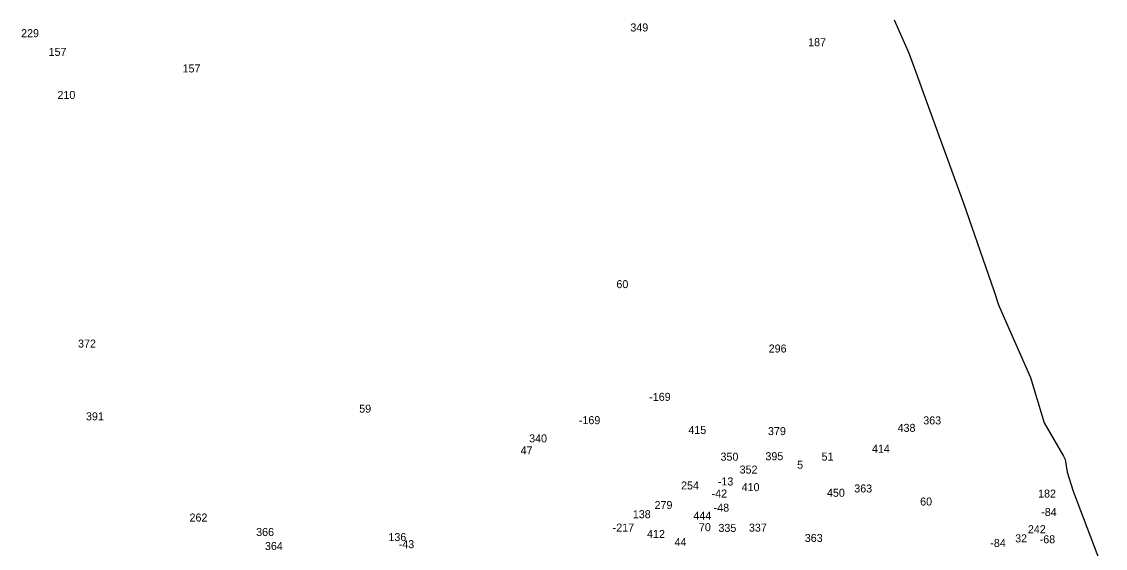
# Model space of a CAD drawing. Extents: x -784109 to -782312, y -974244 to -970866.
# Drawn here: x -783385 to -782606, y -972930 to -972551 of the extents above; entities that cross this region are included whole.
import ezdxf

# ---------------------------------------------------------------- set-up
doc = ezdxf.new("R2010")
doc.units = 0
doc.layers.add('Vrstva 13', color=7, linetype='Continuous')
doc.layers.add('Vrstva 24', color=7, linetype='Continuous')

msp = doc.modelspace()

# ---------------------------------------------------------------- linework, layer by layer
at = {"layer": 'Vrstva 13'}
for p, q in [((-782757.42, -972549.41), (-782746.7, -972573.88)), ((-782746.7, -972573.88), (-782729.15, -972622.14)), ((-782729.15, -972622.14), (-782707.62, -972681.32)), ((-782707.62, -972681.32), (-782685.79, -972744.19)), ((-782685.79, -972744.19), (-782682.37, -972754.55)), ((-782682.37, -972754.55), (-782678.23, -972763.97)), ((-782678.23, -972763.97), (-782659.4, -972806.95)), ((-782659.4, -972806.95), (-782649.62, -972839.48)), ((-782649.62, -972839.48), (-782635.59, -972863.43)), ((-782635.59, -972863.43), (-782634.41, -972866.03)), ((-782634.41, -972866.03), (-782633.06, -972875.09)), ((-782633.06, -972875.09), (-782628.66, -972888.81)), ((-782628.66, -972888.81), (-782605.57, -972949.88))]:
    msp.add_line(p, q, dxfattribs=at)

# ---------------------------------------------------------------- texts
at = {"layer": 'Vrstva 24'}
for s, p in [('349', (-782947.262, -972557.712)), ('229', (-783385.536, -972561.812)), ('187', (-782819.367, -972568.302)), ('157', (-783365.767, -972575.272)), ('157', (-783269.427, -972587.222)), ('210', (-783359.402, -972606.322)), ('60', (-782957.303, -972742.552)), ('372', (-783344.585, -972785.332)), ('296', (-782847.739, -972788.902)), ('-169', (-782933.688, -972823.692)), ('59', (-783142.316, -972832.202)), ('391', (-783338.899, -972837.712)), ('-169', (-782984.3, -972840.48)), ('363', (-782736.546, -972840.652)), ('415', (-782905.511, -972847.542)), ('379', (-782848.248, -972848.372)), ('438', (-782755.008, -972846.032)), ('340', (-783020.075, -972853.592)), ('47', (-783026.221, -972862.262)), ('414', (-782773.467, -972861.052)), ('350', (-782882.409, -972866.802)), ('395', (-782850.086, -972866.442)), ('5', (-782827.293, -972872.572)), ('51', (-782809.675, -972866.702)), ('352', (-782868.643, -972876.072)), ('254', (-782910.768, -972887.502)), ('-13', (-782884.346, -972884.636)), ('410', (-782867.197, -972888.732)), ('-42', (-782888.805, -972893.328)), ('450', (-782805.835, -972892.772)), ('363', (-782786.156, -972889.672)), ('182', (-782653.935, -972893.362)), ('279', (-782929.858, -972901.602)), ('-48', (-782887.352, -972903.492)), ('60', (-782738.793, -972899.072)), ('262', (-783264.386, -972910.622)), ('138', (-782945.485, -972908.192)), ('444', (-782901.899, -972909.282)), ('-84', (-782651.688, -972906.621)), ('-217', (-782959.993, -972917.842)), ('70', (-782897.941, -972917.562)), ('335', (-782883.873, -972918.082)), ('337', (-782861.965, -972917.872)), ('242', (-782661.268, -972919.012)), ('366', (-783216.459, -972921.022)), ('136', (-783121.319, -972924.682)), ('412', (-782935.251, -972922.422)), ('363', (-782821.776, -972925.302)), ('32', (-782670.413, -972925.572)), ('-68', (-782652.788, -972926.263)), ('364', (-783210.142, -972931.112)), ('-43', (-783113.897, -972929.794)), ('44', (-782915.504, -972928.272)), ('-84', (-782688.306, -972928.917))]:
    msp.add_text(s, height=5.76, dxfattribs=at).set_placement(p)

doc.saveas('drawing.dxf')
